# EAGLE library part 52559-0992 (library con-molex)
FFC/FPC-to-Board 0.50mm (.020") SMT, Vertical, ZIF Receptacle Source: http://www.molex.com/product/ffc/52559.html
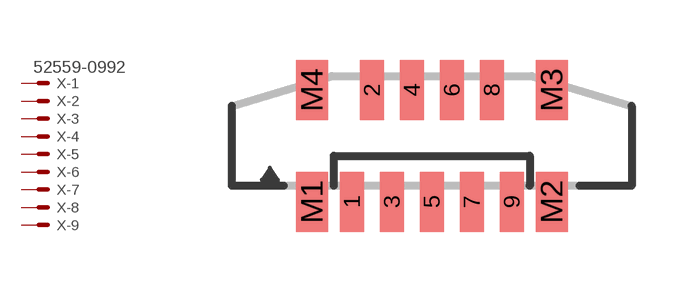
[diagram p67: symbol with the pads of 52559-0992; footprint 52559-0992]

Designator prefix X; gates -1=MV -2=M -3=M -4=M -5=M -6=M -7=M -8=M -9=M

## 52559-0992 (OC_FARNELL: unknown; OC_NEWARK: unknown)  [52559-0992]
1  -1:S  pas
2  -2:S  pas
3  -3:S  pas
4  -4:S  pas
5  -5:S  pas
6  -6:S  pas
7  -7:S  pas
8  -8:S  pas
9  -9:S  pas

## Footprint 52559-0992 (pad centres in mm)
FFC/FPC-to-Board 0.50mm (.020") SMT, Vertical, ZIF Receptacle Source: http://www.molex.com/product/ffc/52559.html
smd 0.6 x 1.5: 1 -2,-1.4; 2 -1.5,1.4; 3 -1,-1.4; 4 -0.5,1.4; 5 0,-1.4; 6 0.5,1.4; 7 1,-1.4; 8 1.5,1.4; 9 2,-1.4
smd 0.8 x 1.5: M1 -3,-1.4; M2 3,-1.4; M3 3,1.4; M4 -3,1.4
